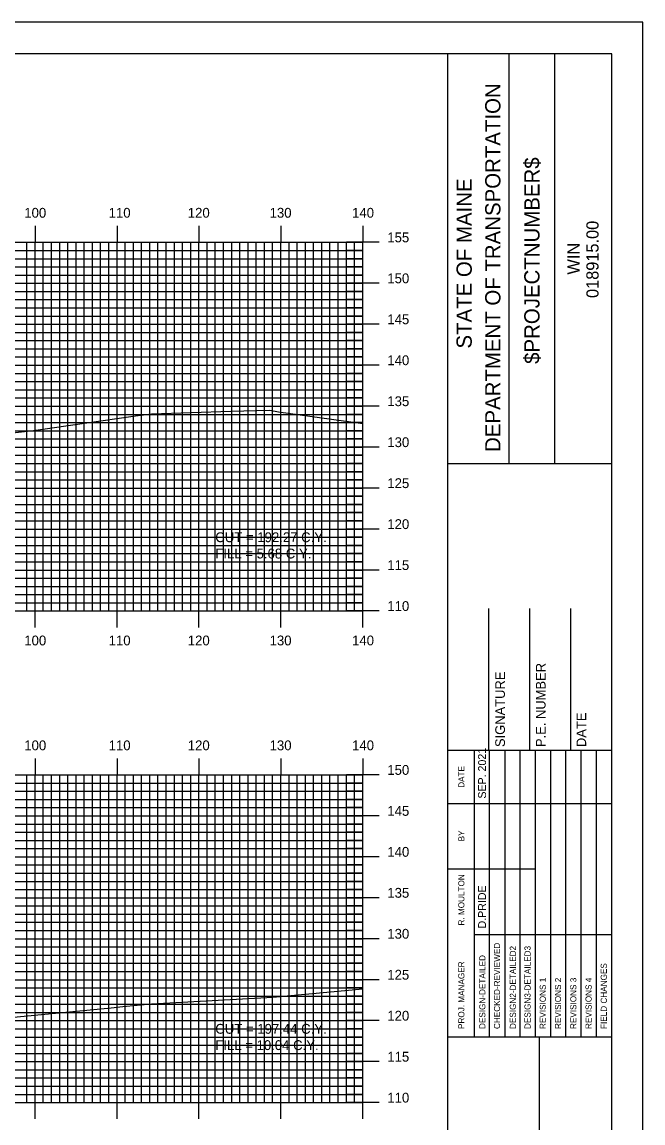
# Model space of a CAD drawing. Extents: x 860258 to 860601, y 364765 to 364985.
# Drawn here: x 860522.3 to 860598.1, y 364850.8 to 364985.2 of the extents above; entities that cross this region are included whole.
import ezdxf

# ---------------------------------------------------------------- set-up
doc = ezdxf.new("R2010")
doc.units = 0
for name, color, linetype in [('BORDER', 7, 'Continuous'), ('D_Text_Standard', 7, 'Continuous'), ('H_V ANNOTATION', 7, 'Continuous'), ('MAJOR', 7, 'Continuous'), ('MINOR', 7, 'Continuous'), ('PLOT BOUNDARY', 7, 'Continuous'), ('S_Roadway_Centerline', 7, 'Continuous')]:
    doc.layers.add(name, color=color, linetype=linetype)

msp = doc.modelspace()

# ---------------------------------------------------------------- linework, layer by layer
at = {"layer": 'BORDER'}
for p, q in [((860574.3, 364771.3), (860574.3, 364981.3)), ((860581.76, 364931.3), (860581.76, 364981.3)), ((860587.35, 364931.3), (860587.35, 364981.3)), ((860574.3, 364931.29), (860594.3, 364931.29)), ((860579.3, 364896.31), (860579.3, 364913.6)), ((860584.3, 364896.31), (860584.3, 364913.6)), ((860589.3, 364896.31), (860589.3, 364913.6)), ((860574.3, 364896.31), (860594.3, 364896.31)), ((860574.3, 364861.31), (860594.3, 364861.31)), ((860585.48, 364791.31), (860585.48, 364861.31))]:
    msp.add_line(p, q, dxfattribs=at)
msp.add_lwpolyline([(860274.3, 364771.3), (860594.3, 364771.3), (860594.3, 364981.3), (860274.3, 364981.3)], close=True, dxfattribs=at)
for points in [[(860577.53, 364889.81), (860577.53, 364896.31)], [(860579.39, 364861.31), (860579.39, 364896.31)], [(860581.26, 364896.31), (860581.26, 364861.31)], [(860583.12, 364861.31), (860583.12, 364896.31)], [(860584.98, 364861.31), (860584.98, 364896.31)], [(860586.85, 364861.31), (860586.85, 364896.31)], [(860588.71, 364861.31), (860588.71, 364896.31)], [(860590.57, 364861.31), (860590.57, 364896.31)], [(860592.44, 364861.31), (860592.44, 364896.31)], [(860577.53, 364861.31), (860577.53, 364894.9)], [(860574.3, 364889.81), (860594.3, 364889.81)], [(860574.3, 364881.81), (860577.53, 364881.81)], [(860577.53, 364881.81), (860584.98, 364881.81)], [(860577.53, 364873.81), (860594.3, 364873.81)]]:
    msp.add_lwpolyline(points, dxfattribs=at)
at = {"layer": 'MAJOR'}
for p, q in [((860523.9, 364960.31), (860523.9, 364958.3)), ((860533.9, 364960.31), (860533.9, 364958.3)), ((860543.9, 364960.31), (860543.9, 364958.3)), ((860553.9, 364960.31), (860553.9, 364958.3)), ((860563.9, 364960.31), (860563.9, 364958.3)), ((860283.9, 364958.3), (860563.9, 364958.3)), ((860283.9, 364958.3), (860563.9, 364958.3)), ((860523.9, 364913.3), (860523.9, 364958.3)), ((860533.9, 364913.3), (860533.9, 364958.3)), ((860543.9, 364913.3), (860543.9, 364958.3)), ((860553.9, 364913.3), (860553.9, 364958.3)), ((860565.9, 364958.3), (860561.9, 364958.3)), ((860563.9, 364913.3), (860563.9, 364958.3)), ((860563.9, 364913.3), (860563.9, 364958.3)), ((860283.9, 364953.3), (860563.9, 364953.3)), ((860565.9, 364953.3), (860561.9, 364953.3)), ((860283.9, 364948.3), (860563.9, 364948.3)), ((860565.9, 364948.3), (860561.9, 364948.3)), ((860283.9, 364943.3), (860563.9, 364943.3)), ((860565.9, 364943.3), (860561.9, 364943.3)), ((860283.9, 364938.3), (860563.9, 364938.3)), ((860565.9, 364938.3), (860561.9, 364938.3)), ((860283.9, 364933.3), (860563.9, 364933.3)), ((860565.9, 364933.3), (860561.9, 364933.3)), ((860283.9, 364928.3), (860563.9, 364928.3)), ((860565.9, 364928.3), (860561.9, 364928.3)), ((860283.9, 364923.3), (860563.9, 364923.3)), ((860565.9, 364923.3), (860561.9, 364923.3)), ((860283.9, 364918.3), (860563.9, 364918.3)), ((860565.9, 364918.3), (860561.9, 364918.3)), ((860283.9, 364913.3), (860563.9, 364913.3)), ((860283.9, 364913.3), (860563.9, 364913.3)), ((860523.9, 364911.3), (860523.9, 364913.3)), ((860533.9, 364911.3), (860533.9, 364913.3)), ((860543.9, 364911.3), (860543.9, 364913.3)), ((860553.9, 364911.3), (860553.9, 364913.3)), ((860565.9, 364913.3), (860561.9, 364913.3)), ((860563.9, 364911.3), (860563.9, 364913.3)), ((860523.9, 364895.31), (860523.9, 364893.3)), ((860533.9, 364895.31), (860533.9, 364893.3)), ((860543.9, 364895.31), (860543.9, 364893.3)), ((860553.9, 364895.31), (860553.9, 364893.3)), ((860563.9, 364895.31), (860563.9, 364893.3)), ((860283.9, 364893.3), (860563.9, 364893.3)), ((860283.9, 364893.3), (860563.9, 364893.3)), ((860523.9, 364853.3), (860523.9, 364893.3)), ((860533.9, 364853.3), (860533.9, 364893.3)), ((860543.9, 364853.3), (860543.9, 364893.3)), ((860553.9, 364853.3), (860553.9, 364893.3)), ((860565.9, 364893.3), (860561.9, 364893.3)), ((860563.9, 364853.3), (860563.9, 364893.3)), ((860563.9, 364853.3), (860563.9, 364893.3)), ((860283.9, 364888.3), (860563.9, 364888.3)), ((860565.9, 364888.3), (860561.9, 364888.3)), ((860283.9, 364883.3), (860563.9, 364883.3)), ((860565.9, 364883.3), (860561.9, 364883.3)), ((860283.9, 364878.3), (860563.9, 364878.3)), ((860565.9, 364878.3), (860561.9, 364878.3)), ((860283.9, 364873.3), (860563.9, 364873.3)), ((860565.9, 364873.3), (860561.9, 364873.3)), ((860283.9, 364868.3), (860563.9, 364868.3)), ((860565.9, 364868.3), (860561.9, 364868.3)), ((860283.9, 364863.3), (860563.9, 364863.3)), ((860565.9, 364863.3), (860561.9, 364863.3)), ((860283.9, 364858.3), (860563.9, 364858.3)), ((860565.9, 364858.3), (860561.9, 364858.3)), ((860283.9, 364853.3), (860563.9, 364853.3)), ((860283.9, 364853.3), (860563.9, 364853.3)), ((860523.9, 364851.3), (860523.9, 364853.3)), ((860533.9, 364851.3), (860533.9, 364853.3)), ((860543.9, 364851.3), (860543.9, 364853.3)), ((860553.9, 364851.3), (860553.9, 364853.3)), ((860565.9, 364853.3), (860561.9, 364853.3)), ((860563.9, 364851.3), (860563.9, 364853.3))]:
    msp.add_line(p, q, dxfattribs=at)
at = {"layer": 'MINOR'}
for p, q in [((860522.9, 364913.3), (860522.9, 364958.3)), ((860524.9, 364913.3), (860524.9, 364958.3)), ((860525.9, 364913.3), (860525.9, 364958.3)), ((860526.9, 364913.3), (860526.9, 364958.3)), ((860527.9, 364913.3), (860527.9, 364958.3)), ((860528.9, 364913.3), (860528.9, 364958.3)), ((860529.9, 364913.3), (860529.9, 364958.3)), ((860530.9, 364913.3), (860530.9, 364958.3)), ((860531.9, 364913.3), (860531.9, 364958.3)), ((860532.9, 364913.3), (860532.9, 364958.3)), ((860534.9, 364913.3), (860534.9, 364958.3)), ((860535.9, 364913.3), (860535.9, 364958.3)), ((860536.9, 364913.3), (860536.9, 364958.3)), ((860537.9, 364913.3), (860537.9, 364958.3)), ((860538.9, 364913.3), (860538.9, 364958.3)), ((860539.9, 364913.3), (860539.9, 364958.3)), ((860540.9, 364913.3), (860540.9, 364958.3)), ((860541.9, 364913.3), (860541.9, 364958.3)), ((860542.9, 364913.3), (860542.9, 364958.3)), ((860544.9, 364913.3), (860544.9, 364958.3)), ((860545.9, 364913.3), (860545.9, 364958.3)), ((860546.9, 364913.3), (860546.9, 364958.3)), ((860547.9, 364913.3), (860547.9, 364958.3)), ((860548.9, 364913.3), (860548.9, 364958.3)), ((860549.9, 364913.3), (860549.9, 364958.3)), ((860550.9, 364913.3), (860550.9, 364958.3)), ((860551.9, 364913.3), (860551.9, 364958.3)), ((860552.9, 364913.3), (860552.9, 364958.3)), ((860554.9, 364913.3), (860554.9, 364958.3)), ((860555.9, 364913.3), (860555.9, 364958.3)), ((860556.9, 364913.3), (860556.9, 364958.3)), ((860557.9, 364913.3), (860557.9, 364958.3)), ((860558.9, 364913.3), (860558.9, 364958.3)), ((860559.9, 364913.3), (860559.9, 364958.3)), ((860560.9, 364913.3), (860560.9, 364958.3)), ((860561.9, 364913.3), (860561.9, 364958.3)), ((860562.9, 364913.3), (860562.9, 364958.3)), ((860283.9, 364957.3), (860563.9, 364957.3)), ((860563.9, 364957.3), (860561.9, 364957.3)), ((860283.9, 364956.3), (860563.9, 364956.3)), ((860283.9, 364955.3), (860563.9, 364955.3)), ((860563.9, 364956.3), (860561.9, 364956.3)), ((860563.9, 364955.3), (860561.9, 364955.3)), ((860283.9, 364954.3), (860563.9, 364954.3)), ((860563.9, 364954.3), (860561.9, 364954.3)), ((860283.9, 364952.3), (860563.9, 364952.3)), ((860283.9, 364951.3), (860563.9, 364951.3)), ((860563.9, 364952.3), (860561.9, 364952.3)), ((860563.9, 364951.3), (860561.9, 364951.3)), ((860283.9, 364950.3), (860563.9, 364950.3)), ((860563.9, 364950.3), (860561.9, 364950.3)), ((860283.9, 364949.3), (860563.9, 364949.3)), ((860563.9, 364949.3), (860561.9, 364949.3)), ((860283.9, 364947.3), (860563.9, 364947.3)), ((860563.9, 364947.3), (860561.9, 364947.3)), ((860283.9, 364946.3), (860563.9, 364946.3)), ((860563.9, 364946.3), (860561.9, 364946.3)), ((860283.9, 364945.3), (860563.9, 364945.3)), ((860563.9, 364945.3), (860561.9, 364945.3)), ((860283.9, 364944.3), (860563.9, 364944.3)), ((860563.9, 364944.3), (860561.9, 364944.3)), ((860283.9, 364942.3), (860563.9, 364942.3)), ((860563.9, 364942.3), (860561.9, 364942.3)), ((860283.9, 364941.3), (860563.9, 364941.3)), ((860563.9, 364941.3), (860561.9, 364941.3)), ((860283.9, 364940.3), (860563.9, 364940.3)), ((860283.9, 364939.3), (860563.9, 364939.3)), ((860563.9, 364940.3), (860561.9, 364940.3)), ((860563.9, 364939.3), (860561.9, 364939.3)), ((860283.9, 364937.3), (860563.9, 364937.3)), ((860563.9, 364937.3), (860561.9, 364937.3)), ((860283.9, 364936.3), (860563.9, 364936.3)), ((860283.9, 364935.3), (860563.9, 364935.3)), ((860563.9, 364936.3), (860561.9, 364936.3)), ((860563.9, 364935.3), (860561.9, 364935.3)), ((860283.9, 364934.3), (860563.9, 364934.3)), ((860563.9, 364934.3), (860561.9, 364934.3)), ((860283.9, 364932.3), (860563.9, 364932.3)), ((860283.9, 364931.3), (860563.9, 364931.3)), ((860563.9, 364932.3), (860561.9, 364932.3)), ((860563.9, 364931.3), (860561.9, 364931.3)), ((860283.9, 364930.3), (860563.9, 364930.3)), ((860563.9, 364930.3), (860561.9, 364930.3)), ((860283.9, 364929.3), (860563.9, 364929.3)), ((860563.9, 364929.3), (860561.9, 364929.3)), ((860283.9, 364927.3), (860563.9, 364927.3)), ((860563.9, 364927.3), (860561.9, 364927.3)), ((860283.9, 364926.3), (860563.9, 364926.3)), ((860563.9, 364926.3), (860561.9, 364926.3)), ((860283.9, 364925.3), (860563.9, 364925.3)), ((860283.9, 364924.3), (860563.9, 364924.3)), ((860563.9, 364925.3), (860561.9, 364925.3)), ((860563.9, 364924.3), (860561.9, 364924.3)), ((860283.9, 364922.3), (860563.9, 364922.3)), ((860563.9, 364922.3), (860561.9, 364922.3)), ((860283.9, 364921.3), (860563.9, 364921.3)), ((860283.9, 364920.3), (860563.9, 364920.3)), ((860563.9, 364921.3), (860561.9, 364921.3)), ((860563.9, 364920.3), (860561.9, 364920.3)), ((860283.9, 364919.3), (860563.9, 364919.3)), ((860563.9, 364919.3), (860561.9, 364919.3)), ((860283.9, 364917.3), (860563.9, 364917.3)), ((860283.9, 364916.3), (860563.9, 364916.3)), ((860563.9, 364917.3), (860561.9, 364917.3)), ((860563.9, 364916.3), (860561.9, 364916.3)), ((860283.9, 364915.3), (860563.9, 364915.3)), ((860563.9, 364915.3), (860561.9, 364915.3)), ((860283.9, 364914.3), (860563.9, 364914.3)), ((860563.9, 364914.3), (860561.9, 364914.3)), ((860283.9, 364892.3), (860563.9, 364892.3)), ((860522.9, 364853.3), (860522.9, 364893.3)), ((860524.9, 364853.3), (860524.9, 364893.3)), ((860525.9, 364853.3), (860525.9, 364893.3)), ((860526.9, 364853.3), (860526.9, 364893.3)), ((860527.9, 364853.3), (860527.9, 364893.3)), ((860528.9, 364853.3), (860528.9, 364893.3)), ((860529.9, 364853.3), (860529.9, 364893.3)), ((860530.9, 364853.3), (860530.9, 364893.3)), ((860531.9, 364853.3), (860531.9, 364893.3)), ((860532.9, 364853.3), (860532.9, 364893.3)), ((860534.9, 364853.3), (860534.9, 364893.3)), ((860535.9, 364853.3), (860535.9, 364893.3)), ((860536.9, 364853.3), (860536.9, 364893.3)), ((860537.9, 364853.3), (860537.9, 364893.3)), ((860538.9, 364853.3), (860538.9, 364893.3)), ((860539.9, 364853.3), (860539.9, 364893.3)), ((860540.9, 364853.3), (860540.9, 364893.3)), ((860541.9, 364853.3), (860541.9, 364893.3)), ((860542.9, 364853.3), (860542.9, 364893.3)), ((860544.9, 364853.3), (860544.9, 364893.3)), ((860545.9, 364853.3), (860545.9, 364893.3)), ((860546.9, 364853.3), (860546.9, 364893.3)), ((860547.9, 364853.3), (860547.9, 364893.3)), ((860548.9, 364853.3), (860548.9, 364893.3)), ((860549.9, 364853.3), (860549.9, 364893.3)), ((860550.9, 364853.3), (860550.9, 364893.3)), ((860551.9, 364853.3), (860551.9, 364893.3)), ((860552.9, 364853.3), (860552.9, 364893.3)), ((860554.9, 364853.3), (860554.9, 364893.3)), ((860555.9, 364853.3), (860555.9, 364893.3)), ((860556.9, 364853.3), (860556.9, 364893.3)), ((860557.9, 364853.3), (860557.9, 364893.3)), ((860558.9, 364853.3), (860558.9, 364893.3)), ((860559.9, 364853.3), (860559.9, 364893.3)), ((860560.9, 364853.3), (860560.9, 364893.3)), ((860561.9, 364853.3), (860561.9, 364893.3)), ((860563.9, 364892.3), (860561.9, 364892.3)), ((860562.9, 364853.3), (860562.9, 364893.3)), ((860283.9, 364891.3), (860563.9, 364891.3)), ((860563.9, 364891.3), (860561.9, 364891.3)), ((860283.9, 364890.3), (860563.9, 364890.3)), ((860563.9, 364890.3), (860561.9, 364890.3)), ((860283.9, 364889.3), (860563.9, 364889.3)), ((860563.9, 364889.3), (860561.9, 364889.3)), ((860283.9, 364887.3), (860563.9, 364887.3)), ((860563.9, 364887.3), (860561.9, 364887.3)), ((860283.9, 364886.3), (860563.9, 364886.3)), ((860283.9, 364885.3), (860563.9, 364885.3)), ((860563.9, 364886.3), (860561.9, 364886.3)), ((860563.9, 364885.3), (860561.9, 364885.3)), ((860283.9, 364884.3), (860563.9, 364884.3)), ((860563.9, 364884.3), (860561.9, 364884.3)), ((860283.9, 364882.3), (860563.9, 364882.3)), ((860283.9, 364881.3), (860563.9, 364881.3)), ((860563.9, 364882.3), (860561.9, 364882.3)), ((860563.9, 364881.3), (860561.9, 364881.3)), ((860283.9, 364880.3), (860563.9, 364880.3)), ((860563.9, 364880.3), (860561.9, 364880.3)), ((860283.9, 364879.3), (860563.9, 364879.3)), ((860563.9, 364879.3), (860561.9, 364879.3)), ((860283.9, 364877.3), (860563.9, 364877.3)), ((860563.9, 364877.3), (860561.9, 364877.3)), ((860283.9, 364876.3), (860563.9, 364876.3)), ((860563.9, 364876.3), (860561.9, 364876.3)), ((860283.9, 364875.3), (860563.9, 364875.3)), ((860563.9, 364875.3), (860561.9, 364875.3)), ((860283.9, 364874.3), (860563.9, 364874.3)), ((860563.9, 364874.3), (860561.9, 364874.3)), ((860283.9, 364872.3), (860563.9, 364872.3)), ((860563.9, 364872.3), (860561.9, 364872.3)), ((860283.9, 364871.3), (860563.9, 364871.3)), ((860563.9, 364871.3), (860561.9, 364871.3)), ((860283.9, 364870.3), (860563.9, 364870.3)), ((860283.9, 364869.3), (860563.9, 364869.3)), ((860563.9, 364870.3), (860561.9, 364870.3)), ((860563.9, 364869.3), (860561.9, 364869.3)), ((860283.9, 364867.3), (860563.9, 364867.3)), ((860563.9, 364867.3), (860561.9, 364867.3)), ((860283.9, 364866.3), (860563.9, 364866.3)), ((860283.9, 364865.3), (860563.9, 364865.3)), ((860563.9, 364866.3), (860561.9, 364866.3)), ((860563.9, 364865.3), (860561.9, 364865.3)), ((860283.9, 364864.3), (860563.9, 364864.3)), ((860563.9, 364864.3), (860561.9, 364864.3)), ((860283.9, 364862.3), (860563.9, 364862.3)), ((860283.9, 364861.3), (860563.9, 364861.3)), ((860563.9, 364862.3), (860561.9, 364862.3)), ((860563.9, 364861.3), (860561.9, 364861.3)), ((860283.9, 364860.3), (860563.9, 364860.3)), ((860563.9, 364860.3), (860561.9, 364860.3)), ((860283.9, 364859.3), (860563.9, 364859.3)), ((860563.9, 364859.3), (860561.9, 364859.3)), ((860283.9, 364857.3), (860563.9, 364857.3)), ((860563.9, 364857.3), (860561.9, 364857.3)), ((860283.9, 364856.3), (860563.9, 364856.3)), ((860563.9, 364856.3), (860561.9, 364856.3)), ((860283.9, 364855.3), (860563.9, 364855.3)), ((860563.9, 364855.3), (860561.9, 364855.3)), ((860283.9, 364854.3), (860563.9, 364854.3)), ((860563.9, 364854.3), (860561.9, 364854.3))]:
    msp.add_line(p, q, dxfattribs=at)
at = {"layer": 'PLOT BOUNDARY'}
msp.add_lwpolyline([(860258.11, 364765.18), (860598.11, 364765.18), (860598.11, 364985.18), (860258.11, 364985.18)], close=True, dxfattribs=at)
at = {"layer": 'S_Roadway_Centerline'}
for points in [[(860446.58, 364943.76), (860452.1, 364940.82), (860462.33, 364936.47), (860469.34, 364933.29), (860472.69, 364931.93), (860473.57, 364931.92), (860479.63, 364930.64), (860482.76, 364931.42), (860484.56, 364931.81), (860498.25, 364932.79), (860509.33, 364933.74), (860523.71, 364935.34), (860536.17, 364937.13), (860538.13, 364937.35), (860547.8, 364937.69), (860552.56, 364937.79), (860553.61, 364937.62), (860563.9, 364936.19)], [(860432.09, 364887.3), (860483.02, 364864.87), (860488.04, 364862.6), (860489.08, 364862.42), (860493.01, 364861.83), (860503.14, 364863.66), (860504.32, 364863.86), (860518.6, 364863.54), (860519.1, 364863.54), (860533.18, 364864.85), (860534.62, 364865.01), (860538.09, 364865.36), (860552.94, 364866.16), (860563.9, 364867.17)]]:
    msp.add_lwpolyline(points, dxfattribs=at)

# ---------------------------------------------------------------- texts
at = {"layer": 'BORDER'}
for s, height, p in [('DEPARTMENT OF TRANSPORTATION', 1.8635, (860580.71, 364932.71)), ('$PROJECTNUMBER$', 1.8635, (860585.48, 364943.46)), ('STATE OF MAINE', 1.8635, (860577.21, 364945.33)), ('018915.00', 1.491, (860592.69, 364951.5)), ('WIN', 1.491, (860590.37, 364954.36)), ('P.E. NUMBER', 1.1811, (860586.22, 364896.69)), ('SIGNATURE', 1.181, (860581.26, 364896.69)), ('DATE', 1.181, (860591.18, 364896.69)), ('SEP. 2021', 0.969, (860578.95, 364890.4)), ('DATE', 0.743, (860576.31, 364891.72)), ('BY', 0.743, (860576.31, 364885.18)), ('R. MOULTON', 0.745, (860576.31, 364874.91)), ('D.PRIDE', 0.969, (860578.95, 364874.55)), ('CHECKED-REVIEWED', 0.7455, (860580.66, 364862.28)), ('DESIGN2-DETAILED2', 0.7455, (860582.6, 364862.28)), ('DESIGN3-DETAILED3', 0.7455, (860584.39, 364862.28)), ('DESIGN-DETAILED', 0.7455, (860578.87, 364862.28)), ('PROJ. MANAGER', 0.7455, (860576.31, 364862.28)), ('FIELD CHANGES', 0.7455, (860593.7, 364862.28)), ('REVISIONS 1', 0.7455, (860586.25, 364862.28)), ('REVISIONS 2', 0.7455, (860588.11, 364862.28)), ('REVISIONS 3', 0.7455, (860589.98, 364862.28)), ('REVISIONS 4', 0.7455, (860591.84, 364862.28))]:
    msp.add_text(s, height=height, rotation=90, dxfattribs=at).set_placement(p)
at = {"layer": 'D_Text_Standard'}
for s, p in [('CUT = 192.27 C.Y.', (860545.9, 364921.7)), ('FILL = 5.68 C.Y.', (860545.9, 364919.71)), ('CUT = 197.44 C.Y.', (860545.9, 364861.7)), ('FILL = 10.04 C.Y.', (860545.9, 364859.71))]:
    msp.add_text(s, height=1.2, dxfattribs=at).set_placement(p)
at = {"layer": 'H_V ANNOTATION'}
for s, p in [('100', (860522.58, 364961.3)), ('110', (860532.88, 364961.3)), ('120', (860542.54, 364961.3)), ('130', (860552.53, 364961.3)), ('140', (860562.6, 364961.3)), ('155', (860566.9, 364958.3)), ('150', (860566.9, 364953.3)), ('145', (860566.9, 364948.3)), ('140', (860566.9, 364943.3)), ('135', (860566.9, 364938.3)), ('130', (860566.9, 364933.3)), ('125', (860566.9, 364928.3)), ('120', (860566.9, 364923.3)), ('115', (860566.9, 364918.3)), ('110', (860566.9, 364913.3)), ('100', (860522.58, 364909.1)), ('110', (860532.88, 364909.1)), ('120', (860542.54, 364909.1)), ('130', (860552.53, 364909.1)), ('140', (860562.6, 364909.1)), ('100', (860522.58, 364896.3)), ('110', (860532.88, 364896.3)), ('120', (860542.54, 364896.3)), ('130', (860552.53, 364896.3)), ('140', (860562.6, 364896.3)), ('150', (860566.9, 364893.3)), ('145', (860566.9, 364888.3)), ('140', (860566.9, 364883.3)), ('135', (860566.9, 364878.3)), ('130', (860566.9, 364873.3)), ('125', (860566.9, 364868.3)), ('120', (860566.9, 364863.3)), ('115', (860566.9, 364858.3)), ('110', (860566.9, 364853.3))]:
    msp.add_text(s, height=1.2, dxfattribs=at).set_placement(p)

doc.saveas('drawing.dxf')
